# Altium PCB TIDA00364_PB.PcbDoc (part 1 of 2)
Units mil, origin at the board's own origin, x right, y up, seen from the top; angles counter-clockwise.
Board outline 10630 x 4425 mil, 2 copper layers (Top Layer, Metal), stack 128.78 mil thick; 244 components, 79 nets, 527 pads, 0 vias.
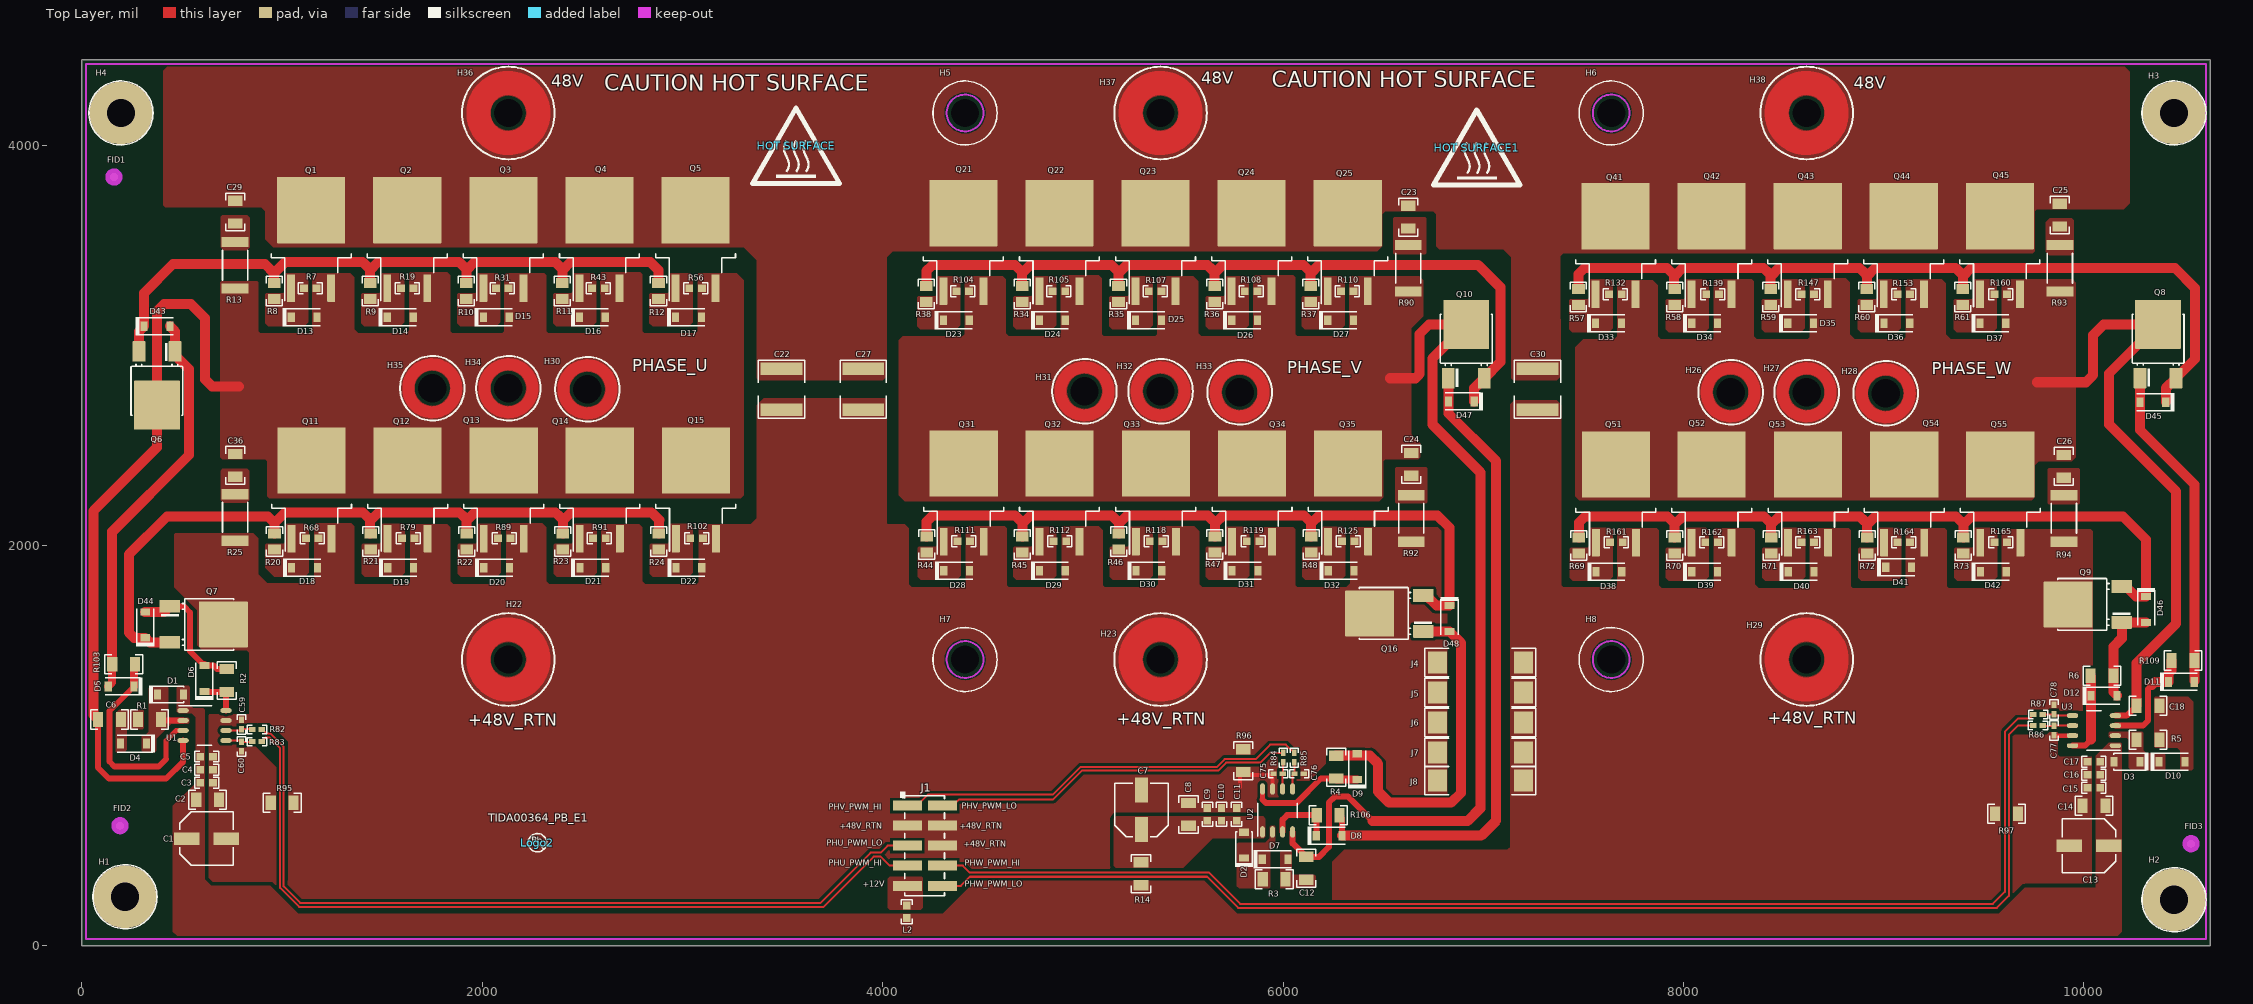
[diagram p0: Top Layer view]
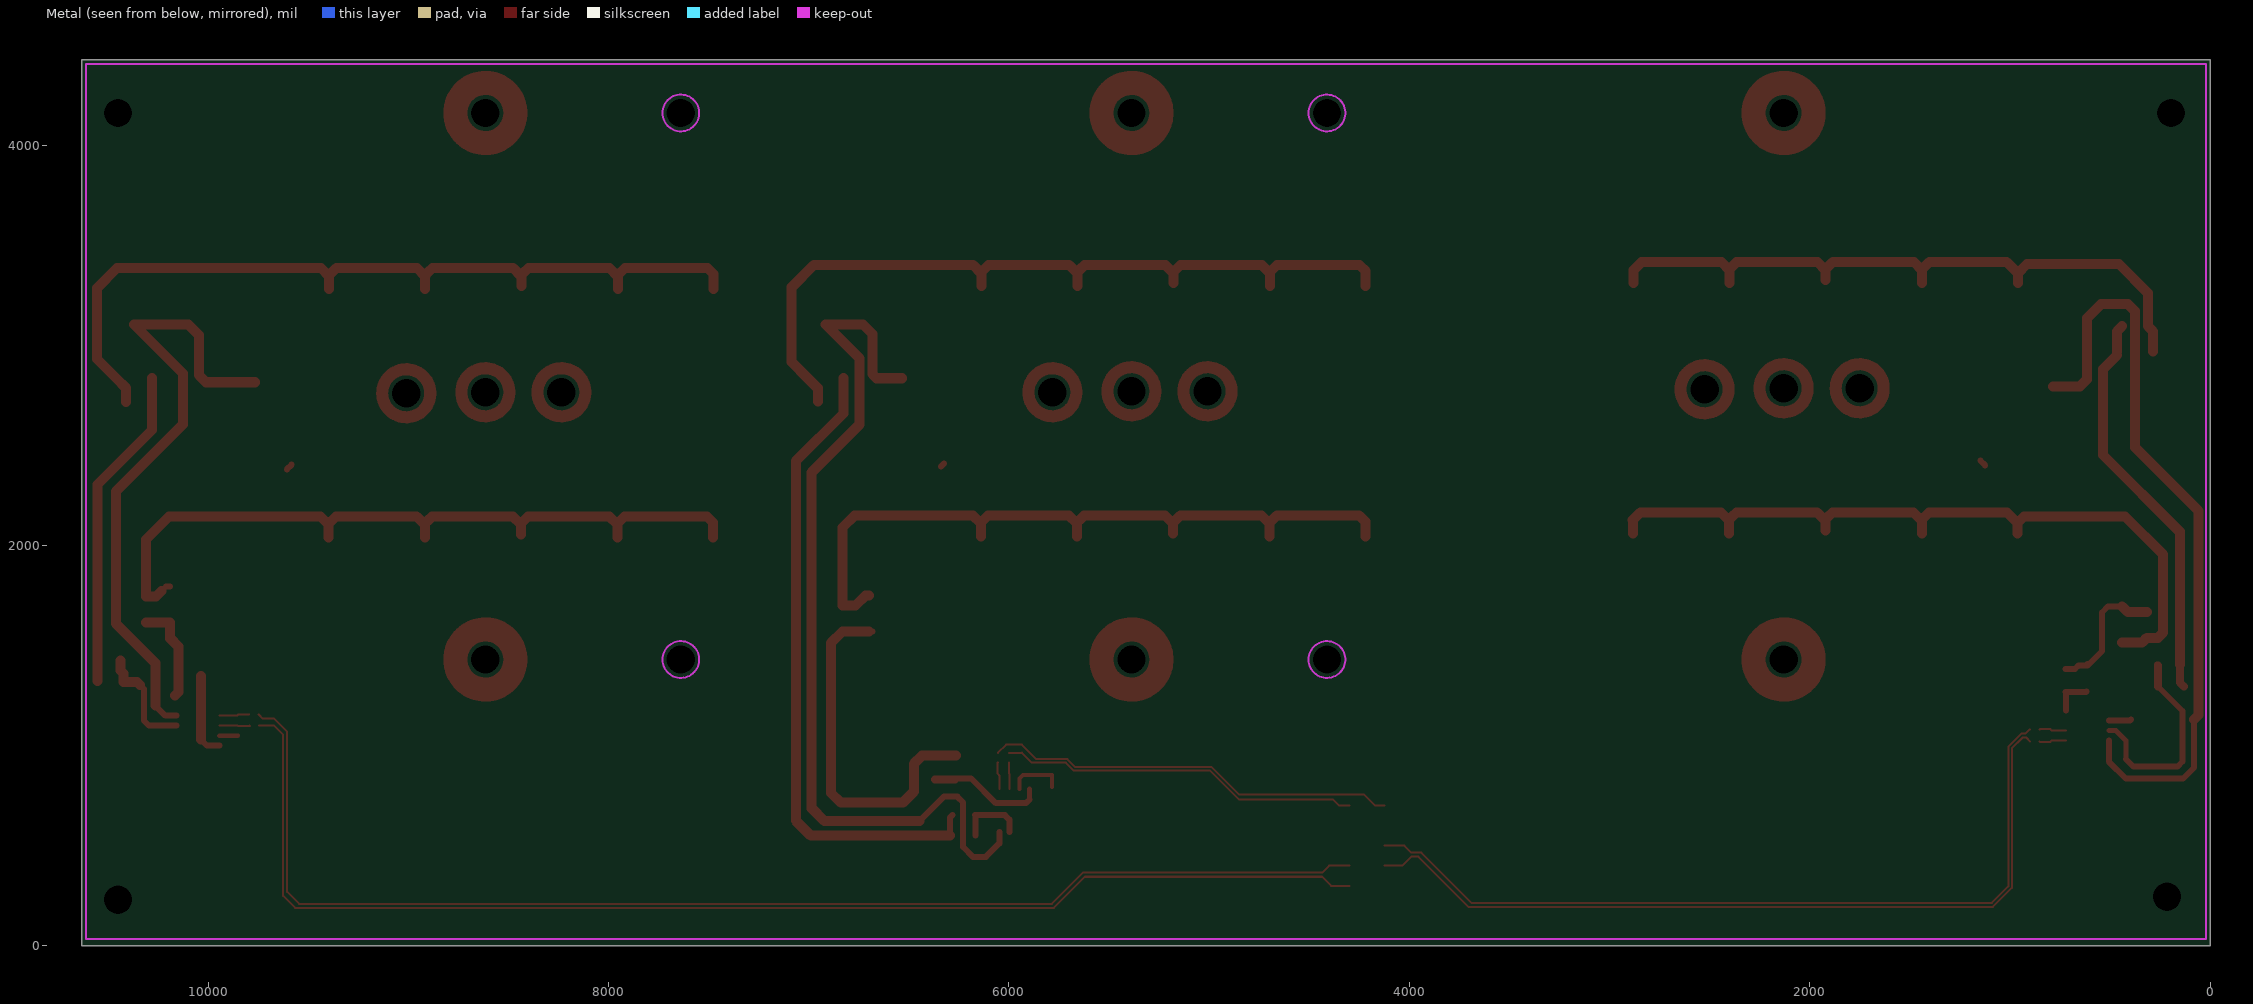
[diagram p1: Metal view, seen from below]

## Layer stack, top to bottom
Top Solder: solder mask 0.4, Solder Resist, Dk 3.5
Top Layer: signal copper 2.8
Dielectric1: core 7.87, Isolated Thermal conductive, Dk 4.8
Metal: signal copper 118.11
Bottom Solder: solder mask 0.4, Solder Resist, Dk 3.5

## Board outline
0,0 0,4425 10630,4425 10630,0

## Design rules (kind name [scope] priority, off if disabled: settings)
AcuteAngle [All] p1: minimum=4.50000000000000E+0001 checktracksonly=FALSE
AssemblyTestPointUsage [All] p1: valid=2
Clearance Clearance_PhaseW [(InNet('PHASE_W') AND InNet('PHW_PWM_HI_DRV'))] p1: gap=30
Clearance Clearance_PhaseV [(InNet('PHASE_V') AND InNet('PHV_PWM_HI_DRV'))] p2: gap=30
Clearance Clearance_phaseU [(InNet('PHASE_U') AND InNet('PHU_PWM_HI_DRV'))] p3: gap=30
Clearance Clearance_keepout [IsKeepOut vs InPolygon] p4: gap=5
Clearance Clearance_MTG_COPPER [InPadClass('MTG') vs InPolygon] p5: gap=40
Clearance "Shape to Shape" [InPolygon vs InPolygon] p6: gap=20
Clearance "shape to all" [InPolygon] p7: gap=15
Clearance Clearance_Boardedge_poly [OnCopper and InPolygon vs IsKeepOut] p8: gap=15
Clearance "Clearance_via_thr pin" [IsVia vs IsThruPin] p9: gap=8
Clearance "Clearance_pad _class" [InPadClass('u12,u4,u5')] p10: gap=7.8
Clearance "SMD to Via" [IsSMTPin vs IsVia] p11: gap=8
Clearance [All] p12: gap=8
Clearance Clearance_U5 [InPadClass('u12,u4,u5') vs IsPad] p13: gap=7.87
DiffPairsRouting DiffPair_DiffPairsRouting [InDifferentialPair ('kan')] p1: maxlimit=10 minlimit=10 mostfreqgap=10 toplayer_minwidth=15 toplayer_maxwidth=15 toplayer_prefwidth=15 bottomlayer_minwidth=15 bottomlayer_maxwidth=15 bottomlayer_prefwidth=15 maxuncoupledlength=500
DiffPairsRouting DiffPair_DiffPairsRouting_1 [InDifferentialPair ('kan')] p2: maxlimit=10 minlimit=10 mostfreqgap=10 toplayer_minwidth=15 toplayer_maxwidth=15 toplayer_prefwidth=15 bottomlayer_minwidth=15 bottomlayer_maxwidth=15 bottomlayer_prefwidth=15 maxuncoupledlength=500
DiffPairsRouting [All] p3: maxlimit=100 minlimit=10 mostfreqgap=10 toplayer_minwidth=15 toplayer_maxwidth=15 toplayer_prefwidth=15 bottomlayer_minwidth=15 bottomlayer_maxwidth=15 bottomlayer_prefwidth=15 maxuncoupledlength=1000
FabricationTestPointUsage TestPointUsage [All] p1: valid=2 allowmultiple=FALSE
FabricationTestpoint Testpoint [All] p1: side=3 testpointundercomponent=TRUE minsize=40 maxsize=100 preferedsize=60 minholesize=0 maxholesize=40 preferedholesize=32 testpointgrid=1 allowsidetop=TRUE allowsidebottom=TRUE usegrid=TRUE gridtolerance=0.01
FanoutControl Fanout_LCC [IsLCC] p1: bgadir=Out bgaviamode=Centered fanoutstyle=Auto fanoutdirection=Alternating viagrid=1 // Fanout_LCC (Default Rule)
FanoutControl Fanout_BGA [IsBGA] p2: bgadir=Out bgaviamode=Centered fanoutstyle=Auto fanoutdirection=Alternating viagrid=1 // Fanout_BGA (Default Rule)
FanoutControl Fanout_Default [All] p4: bgadir=Out bgaviamode=Centered fanoutstyle=Auto fanoutdirection=Alternating viagrid=1 // Fanout_Default (Default Rule)
FanoutControl Fanout_Small [(CompPinCount < 5)] p5: bgadir=Out bgaviamode=Centered fanoutstyle=Auto fanoutdirection=OutThenIn viagrid=1 // Fanout_Small (Default Rule)
HoleSize [All] p1: absolutevalues=TRUE maxlimit=500 minlimit=7 maxpercent=80.000 minpercent=20.000
MatchedLengths DiffPair_MatchedLengths [InDifferentialPair ('kan')] p1: tolerance=1000 checknetsindiffpair=TRUE checkdiffpairvsdiffpair=FALSE checkxsignals=FALSE checkothers=FALSE
MatchedLengths DiffPair_MatchedLengths_1 [InDifferentialPair ('kan')] p2: tolerance=1000 checknetsindiffpair=TRUE checkdiffpairvsdiffpair=FALSE checkxsignals=FALSE checkothers=FALSE
MinimumAnnularRing [All] p1: minimumring=5
MinimumAnnularRing MinimumAnnularRing_ThermalPadVias [IsVia and InAnyComponent] p2: minimumring=5.91
MinimumSolderMaskSliver MinimumSolderMaskSliver_Logo [InComponentClass('Logo') vs InComponentClass('Logo')] p1: minsoldermaskwidth=0.7
MinimumSolderMaskSliver [All] p2: minsoldermaskwidth=3.94
PlaneClearance [All] p1: clearance=15
PlaneConnect [All] p1: planeconnectstyle=Direct reliefexpansion=10 reliefentries=4 reliefconductorwidth=10 reliefairgap=10
PolygonConnect [All] p1: connectstyle=Direct reliefconductorwidth=10 reliefentries=4 polygonreliefangle="90 Angle" airgapwidth=10
RoutingVias RoutingVias_power [InNetClass('POWER')] p1: holewidth=12 width=24 viastyle="Through Hole" minholewidth=7.87 minwidth=19.68 maxholewidth=24 maxwidth=34
RoutingVias ThermalPadVias [IsVia and InAnyComponent] p2: holewidth=8 width=20 viastyle="Through Hole" minholewidth=7.87 minwidth=19 maxholewidth=24 maxwidth=34
RoutingVias [All] p3: holewidth=16 width=32 viastyle="Through Hole" minholewidth=12 minwidth=24 maxholewidth=24 maxwidth=34
SMDToCorner [All] p1: distance=30000
SilkToSilkClearance [All] p1: silktosilkclearance=5
SilkToSolderMaskClearance SilkscreenOverComponentPads [IsPad] p1: minsilkscreentomaskgap=5 clearancetoexposedcopper=TRUE
SolderMaskExpansion [All] p1: expansion=3
Width Width_power [InNetClass('POWER')] p1: maxlimit=100 minlimit=8 preferedwidth=20
Width [All] p2: maxlimit=900 minlimit=10 preferedwidth=10 checkconnectedcopper=TRUE
16 further rules are at their usual default settings.

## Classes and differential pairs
component class TIDA00364_PB_PhaseW: C25 C26 C30 D33 D34 D35 D36 D37 D38 D39 D40 D41 D42 Q41 Q42 Q43 Q44 Q45 Q51 Q52 Q53 Q54 Q55 R57 R58 R59 R60 R61 R69 R70 R71 R72 R73 R93 R94 R132 R139 R147 R153 R160 R161 R162 R163 R164 R165
component class TIDA00364_PB_PhaseV: C23 C24 C27 D23 D24 D25 D26 D27 D28 D29 D30 D31 D32 Q21 Q22 Q23 Q24 Q25 Q31 Q32 Q33 Q34 Q35 R34 R35 R36 R37 R38 R44 R45 R46 R47 R48 R90 R92 R104 R105 R107 R108 R110 R111 R112 R118 R119 R125
component class TIDA00364_PB_PhaseU: C22 C29 C36 D13 D14 D15 D16 D17 D18 D19 D20 D21 D22 Q1 Q2 Q3 Q4 Q5 Q11 Q12 Q13 Q14 Q15 R7 R8 R9 R10 R11 R12 R13 R19 R20 R21 R22 R23 R24 R25 R31 R43 R56 R68 R79 R89 R91 R102
component class TIDA00364_PB_Hardware: FID1 FID2 FID3 H1 H2 H3 H4 H5 H6 H7 H8 H22 H23 H26 H27 H28 H29 H30 H31 H32 H33 H34 H35 H36 H37 H38 "HOT SURFACE" "HOT SURFACE1" J1 J4 J5 J6 J7 J8 L2 Logo2 R14 ZZ1 ZZ2 ZZ3
component class TIDA00364_PB_GateDriver: C1 C2 C3 C4 C5 C6 C7 C8 C9 C10 C11 C12 C13 C14 C15 C16 C17 C18 C59 C60 C75 C76 C77 C78 D1 D2 D3 D4 D5 D6 D7 D8 D9 D10 D11 D12 D43 D44 D45 D46 D47 D48 Q6 Q7 Q8 Q9 Q10 Q16 R1 R2 R3 R4 R5 R6 R82 R83 R84 R85 R86 R87 R95 R96 R97 R103 R106 R109 U1 U2 U3
component class AssemblyNote: ZZ1 ZZ2 ZZ3
component class FiducialMark: FID1 FID2 FID3
component class Header: J1

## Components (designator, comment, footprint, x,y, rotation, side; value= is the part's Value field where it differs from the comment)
C1 "EEE-FK1V101XP" SM_RADIAL_D8 622.57,535.43 r0 top
C2 "GRM31CR71E475KA88L" 1206 627.57,730.43 r0 top
C3 "C1608X7R1E104K" 0603 622.57,815.43 r180 top
C4 "C1608X7R1H103K" 0603 622.57,880.43 r0 top
C5 "GRM188R71H102KA01D" 0603 622.57,945.43 r0 top
C6 "C3216X7R1H105K160AB" 1206 137.57,1130.43 r180 top
C7 "EEE-FK1V101XP" SM_RADIAL_D8 5292.6,679.24 r90 top
C8 "GRM31CR71E475KA88L" 1206 5527.12,656.24 r90 top
C9 "C1608X7R1E104K" 0603 5622.12,656.24 r270 top
C10 "C1608X7R1H103K" 0603 5692.12,656.24 r90 top
C11 "GRM188R71H102KA01D" 0603 5767.12,656.24 r90 top
C12 "C3216X7R1H105K160AB" 1206 6114.64,387.64 r90 top
C13 "EEE-FK1V101XP" SM_RADIAL_D8 10025,500 r180 top
C14 "GRM31CR71E475KA88L" 1206 10050,700 r180 top
C15 "C1608X7R1E104K" 0603 10050,790 r0 top
C16 "C1608X7R1H103K" 0603 10050,855 r180 top
C17 "GRM188R71H102KA01D" 0603 10050,920 r180 top
C18 "C3216X7R1H105K160AB" 1206 10320,1200 r180 top
C22 "GRM55DR72E105KW01L" 2220_200 3495,2780 r270 top
C23 "GRM31CR72E333KW03L" 1206 6625,3640 r270 top
C24 "GRM31CR72E333KW03L" 1206 6640,2405 r270 top
C25 "GRM31CR72E333KW03L" 1206 9880,3650 r270 top
C26 "GRM31CR72E333KW03L" 1206 9900,2395 r270 top
C27 "GRM55DR72E105KW01L" 2220_200 3902.64,2780 r270 top
C29 "GRM31CR72E333KW03L" 1206 765,3665 r270 top
C30 "GRM55DR72E105KW01L" 2220_200 7270,2780 r270 top
C36 "GRM31CR72E333KW03L" 1206 765,2400 r270 top
C59 "C0402C101J3GACTU" 0402 797.57,1105.43 r90 top
C60 "C0402C101J3GACTU" 0402 797.57,995.43 r270 top
C75 "C0402C101J3GACTU" 0402 5975,860 r180 top
C76 "C0402C101J3GACTU" 0402 6080,860 r0 top
C77 "C0402C101J3GACTU" 0402 9850.5,1075 r270 top
C78 "C0402C101J3GACTU" 0402 9850,1180 r90 top
D1 "MBR2H200SFT1G" SOD-123FL 442.57,1255.43 r0 top
D2 "MBR2H200SFT1G" SOD-123FL 5804.64,502.64 r90 top
D3 "MBR2H200SFT1G" SOD-123FL 10215,920 r180 top
D4 "B0530W-7-F" SOD-123 257.57,1010.43 r180 top
D5 "B0530W-7-F" SOD-123 195.57,1295.43 r180 top
D6 "B0530W-7-F" SOD-123 612,1335 r90 top
D7 "B0530W-7-F" SOD-123 5959.64,432.64 r0 top
D8 "B0530W-7-F" SOD-123 6230,550 r0 top
D9 "B0530W-7-F" SOD-123 6370,895 r90 top
D10 "B0530W-7-F" SOD-123 10440,920 r0 top
D11 "B0530W-7-F" SOD-123 10487,1318 r0 top
D12 "B0530W-7-F" SOD-123 10100,1250 r0 top
D13 "B0530W-7-F" SOD-123 1110,3140 r0 top
D14 "B0530W-7-F" SOD-123 1590,3140 r0 top
D15 "B0530W-7-F" SOD-123 2070,3140 r0 top
D16 "B0530W-7-F" SOD-123 2550,3140 r0 top
D17 "B0530W-7-F" SOD-123 3030,3140 r0 top
D18 "B0530W-7-F" SOD-123 1111.89,1889.21 r0 top
D19 "B0530W-7-F" SOD-123 1591.89,1889.21 r0 top
D20 "B0530W-7-F" SOD-123 2071.89,1889.21 r0 top
D21 "B0530W-7-F" SOD-123 2551.89,1889.21 r0 top
D22 "B0530W-7-F" SOD-123 3031.89,1889.21 r0 top
D23 "B0530W-7-F" SOD-123 4367.64,3125 r0 top
D24 "B0530W-7-F" SOD-123 4847.64,3125 r0 top
D25 "B0530W-7-F" SOD-123 5327.64,3125 r0 top
D26 "B0530W-7-F" SOD-123 5807.64,3125 r0 top
D27 "B0530W-7-F" SOD-123 6287.64,3125 r0 top
D28 "B0530W-7-F" SOD-123 4369.53,1874.21 r0 top
D29 "B0530W-7-F" SOD-123 4847.64,1874.21 r0 top
D30 "B0530W-7-F" SOD-123 5329.53,1874.21 r0 top
D31 "B0530W-7-F" SOD-123 5809.53,1874.21 r0 top
D32 "B0530W-7-F" SOD-123 6289.53,1874.21 r0 top
D33 "B0530W-7-F" SOD-123 7625.28,3110 r0 top
D34 "B0530W-7-F" SOD-123 8105.28,3110 r0 top
D35 "B0530W-7-F" SOD-123 8585.28,3110 r0 top
D36 "B0530W-7-F" SOD-123 9065.28,3110 r0 top
D37 "B0530W-7-F" SOD-123 9545.28,3110 r0 top
D38 "B0530W-7-F" SOD-123 7627.17,1869.21 r0 top
D39 "B0530W-7-F" SOD-123 8105.28,1869.21 r0 top
D40 "B0530W-7-F" SOD-123 8587.17,1869.21 r0 top
D41 "B0530W-7-F" SOD-123 9074.47,1890 r0 top
D42 "B0530W-7-F" SOD-123 9547.17,1869.21 r0 top
D43 "B0530W-7-F" SOD-123 375,3095 r0 top
D44 "B0530W-7-F" SOD-123 316,1603 r90 top
D45 "B0530W-7-F" SOD-123 10344.47,2715.53 r180 top
D46 "B0530W-7-F" SOD-123 10310,1680 r270 top
D47 "B0530W-7-F" SOD-123 6890,2719.06 r180 top
D48 "B0530W-7-F" SOD-123 6830.94,1635 r270 top
FID1 "Fiducial" Fiducial10-20 160,3840 r90 top
FID2 "Fiducial" Fiducial10-20 190,600 r90 top
FID3 "Fiducial" Fiducial10-20 10535,510 r90 top
H1 "RM3X8MM 2701" "APM_RM3X8MM 2701"#1 215,245 r0 top
H2 "RM3X8MM 2701" "APM_RM3X8MM 2701"#1 10450,230 r0 top
H3 "RM3X8MM 2701" "APM_RM3X8MM 2701"#1 10450,4160 r0 top
H4 "RM3X8MM 2701" "APM_RM3X8MM 2701"#1 195,4160 r0 top
H5 "RM3X8MM 2701" "APM_RM3X8MM 2701"#2 4411,4160 r0 top
H6 "RM3X8MM 2701" "APM_RM3X8MM 2701"#2 7638.36,4160 r0 top
H7 "RM3X8MM 2701" "APM_RM3X8MM 2701"#2 4411,1430 r0 top
H8 "RM3X8MM 2701" "APM_RM3X8MM 2701"#2 7638.36,1430 r0 top
H22 "24438" Keystone24438 2130,1430 r0 top
H23 "24438" Keystone24438 5387.64,1430 r0 top
H26 "24438" Keystone24438 8235,2765 r0 top
H27 "24438" Keystone24438 8615,2765 r0 top
H28 "24438" Keystone24438 9010,2760 r0 top
H29 "24438" Keystone24438 8615,1430 r0 top
H30 "24438" Keystone24438 2525,2780 r0 top
H31 "24438" Keystone24438 5007.64,2770 r0 top
H32 "24438" Keystone24438 5387.64,2770 r0 top
H33 "24438" Keystone24438 5782.64,2765 r0 top
H34 "24438" Keystone24438 2130,2785 r0 top
H35 "24438" Keystone24438 1750,2785 r0 top
H36 "24438" Keystone24438 2130,4160 r0 top
H37 "24438" Keystone24438 5387.64,4160 r0 top
H38 "24438" Keystone24438 8615,4160 r0 top
"HOT SURFACE" "CAUTION HOT SURFACE" IEC_HotSurface_medium 3567,3996 r0 top
"HOT SURFACE1" "CAUTION HOT SURFACE" IEC_HotSurface_medium 6967,3987 r0 top
J1 "0015910100" Molex_0015910100 4210,500 r270 top
J4 "S1621-46R" Harwin_S1621-46R 6985,1415 r0 top
J5 "S1621-46R" Harwin_S1621-46R 6985,1265 r0 top
J6 "S1621-46R" Harwin_S1621-46R 6985,1115 r0 top
J7 "S1621-46R" Harwin_S1621-46R 6985,965 r0 top
J8 "S1621-46R" Harwin_S1621-46R 6985,825 r0 top
L2 "BLM18HE152SN1D" 0603 4120,170 r270 top
Logo2 "Pb-Free Symbol" Pb-Free_Overlay_Small 2275,515 r0 top
Q1 "CSD19536KTT" KTT0002A_N 1145,3527 r90 top
Q2 "CSD19536KTT" KTT0002A_N 1625,3527 r90 top
Q3 "CSD19536KTT" KTT0002A_N 2105,3527 r90 top
Q4 "CSD19536KTT" KTT0002A_N 2585,3527 r90 top
Q5 "CSD19536KTT" KTT0002A_N 3065,3527 r90 top
Q6 "MJD45H11RLG" DPAK 375,2835 r270 top
Q7 "MJD45H11RLG" DPAK 572.57,1605.43 r0 top
Q8 "MJD45H11RLG" DPAK 10370,2970 r90 top
Q9 "MJD45H11RLG" DPAK 10055,1705 r180 top
Q10 "MJD45H11RLG" DPAK 6914.8,2969.06 r90 top
Q11 "CSD19536KTT" KTT0002A_N 1146.89,2276.21 r90 top
Q12 "CSD19536KTT" KTT0002A_N 1626.89,2276.21 r90 top
Q13 "CSD19536KTT" KTT0002A_N 2106.89,2276.21 r90 top
Q14 "CSD19536KTT" KTT0002A_N 2586.89,2276.21 r90 top
Q15 "CSD19536KTT" KTT0002A_N 3066.89,2276.21 r90 top
Q16 "MJD45H11RLG" DPAK 6565.94,1660 r180 top
Q21 "CSD19536KTT" KTT0002A_N 4402.64,3512 r90 top
Q22 "CSD19536KTT" KTT0002A_N 4882.64,3512 r90 top
Q23 "CSD19536KTT" KTT0002A_N 5362.64,3512 r90 top
Q24 "CSD19536KTT" KTT0002A_N 5842.64,3512 r90 top
Q25 "CSD19536KTT" KTT0002A_N 6322.64,3512 r90 top
Q31 "CSD19536KTT" KTT0002A_N 4404.53,2261.21 r90 top
Q32 "CSD19536KTT" KTT0002A_N 4882.64,2261.21 r90 top
Q33 "CSD19536KTT" KTT0002A_N 5364.53,2261.21 r90 top
Q34 "CSD19536KTT" KTT0002A_N 5844.53,2261.21 r90 top
Q35 "CSD19536KTT" KTT0002A_N 6324.53,2261.21 r90 top
Q41 "CSD19536KTT" KTT0002A_N 7660.28,3497 r90 top
Q42 "CSD19536KTT" KTT0002A_N 8140.28,3497 r90 top
Q43 "CSD19536KTT" KTT0002A_N 8620.28,3497 r90 top
Q44 "CSD19536KTT" KTT0002A_N 9100.28,3497 r90 top
Q45 "CSD19536KTT" KTT0002A_N 9580.28,3497 r90 top
Q51 "CSD19536KTT" KTT0002A_N 7662.17,2256.21 r90 top
Q52 "CSD19536KTT" KTT0002A_N 8140.28,2256.21 r90 top
Q53 "CSD19536KTT" KTT0002A_N 8622.17,2256.21 r90 top
Q54 "CSD19536KTT" KTT0002A_N 9102.17,2256.21 r90 top
Q55 "CSD19536KTT" KTT0002A_N 9582.17,2256.21 r90 top
R1 "CRCW12062R00FKEA" 1206 337.57,1130.43 r180 top
R2 "CRCW120624R0JNEA" 1206 722.57,1325.43 r90 top
R3 "CRCW12062R00FKEA" 1206 5955,332.64 r0 top
R4 "CRCW120624R0JNEA" 1206 6265,892.64 r90 top
R5 "CRCW12062R00FKEA" 1206 10320,1030 r0 top
R6 "CRCW120624R0JNEA" 1206 10090,1350 r0 top
R7 "CRCW060310K0FKEA" 0603 1140,3285 r180 top
R8 "CRCW08058R20JNEA" 0805_HV 960,3270 r90 top
R9 "CRCW08058R20JNEA" 0805_HV 1440,3270 r90 top
R10 "CRCW08058R20JNEA" 0805_HV 1920,3270 r90 top
R11 "CRCW08058R20JNEA" 0805_HV 2400,3270 r90 top
R12 "CRCW08058R20JNEA" 0805_HV 2880,3270 r90 top
R13 "CRCW25121R00FKEG" 2512 765,3400 r90 top
R14 "CRCW12060000Z0EA" 1206 5290,360 r90 top
R19 "CRCW060310K0FKEA" 0603 1625,3285 r180 top
R20 "CRCW08058R20JNEA" 0805_HV 961.89,2019.21 r90 top
R21 "CRCW08058R20JNEA" 0805_HV 1441.89,2019.21 r90 top
R22 "CRCW08058R20JNEA" 0805_HV 1921.89,2019.21 r90 top
R23 "CRCW08058R20JNEA" 0805_HV 2401.89,2019.21 r90 top
R24 "CRCW08058R20JNEA" 0805_HV 2881.89,2019.21 r90 top
R25 "CRCW25121R00FKEG" 2512 765,2140 r90 top
R31 "CRCW060310K0FKEA" 0603 2100,3285 r180 top
R34 "CRCW08058R20JNEA" 0805_HV 4697.64,3255 r90 top
R35 "CRCW08058R20JNEA" 0805_HV 5177.64,3255 r90 top
R36 "CRCW08058R20JNEA" 0805_HV 5657.64,3255 r90 top
R37 "CRCW08058R20JNEA" 0805_HV 6137.64,3255 r90 top
R38 "CRCW08058R20JNEA" 0805_HV 4217.64,3255 r90 top
R43 "CRCW060310K0FKEA" 0603 2580,3285 r180 top
R44 "CRCW08058R20JNEA" 0805_HV 4219.53,2004.21 r90 top
R45 "CRCW08058R20JNEA" 0805_HV 4697.64,2004.21 r90 top
R46 "CRCW08058R20JNEA" 0805_HV 5179.53,2019.21 r90 top
R47 "CRCW08058R20JNEA" 0805_HV 5659.53,2004.21 r90 top
R48 "CRCW08058R20JNEA" 0805_HV 6139.53,2004.21 r90 top
R56 "CRCW060310K0FKEA" 0603 3065,3285 r180 top
R57 "CRCW08058R20JNEA" 0805_HV 7475.28,3240 r90 top
R58 "CRCW08058R20JNEA" 0805_HV 7955.28,3240 r90 top
R59 "CRCW08058R20JNEA" 0805_HV 8435.28,3240 r90 top
R60 "CRCW08058R20JNEA" 0805_HV 8915.28,3240 r90 top
R61 "CRCW08058R20JNEA" 0805_HV 9395.28,3240 r90 top
R68 "CRCW060310K0FKEA" 0603 1150,2035 r180 top
R69 "CRCW08058R20JNEA" 0805_HV 7477.17,1999.21 r90 top
R70 "CRCW08058R20JNEA" 0805_HV 7955.28,1999.21 r90 top
R71 "CRCW08058R20JNEA" 0805_HV 8437.17,1999.21 r90 top
R72 "CRCW08058R20JNEA" 0805_HV 8917.17,1999.21 r90 top
R73 "CRCW08058R20JNEA" 0805_HV 9397.17,1999.21 r90 top
R79 "CRCW060310K0FKEA" 0603 1630,2035 r180 top
R82 "CRCW04022K00FKED" 0402 875,1080 r0 top
R83 "CRCW04022K00FKED" 0402 875,1020 r0 top
R84 "CRCW04022K00FKED" 0402 6000,940 r90 top
R85 "CRCW04022K00FKED" 0402 6055,940 r90 top
R86 "CRCW04022K00FKED" 0402 9770,1100 r180 top
R87 "CRCW04022K00FKED" 0402 9771.13,1155.39 r180 top
R89 "CRCW060310K0FKEA" 0603 2110,2035 r180 top
R90 "CRCW25121R00FKEG" 2512 6625,3385 r90 top
R91 "CRCW060310K0FKEA" 0603 2585,2035 r180 top
R92 "CRCW25121R00FKEG" 2512 6640,2135 r90 top
R93 "CRCW25121R00FKEG" 2512 9880,3385 r90 top
R94 "CRCW25121R00FKEG" 2512 9900,2135 r90 top
R95 "CRCW12060000Z0EA" 1206 1000,715 r0 top
R96 "CRCW12060000Z0EA" 1206 5800,925 r90 top
R97 "CRCW12060000Z0EA" 1206 9612.91,660 r180 top
R102 "CRCW060310K0FKEA" 0603 3070,2035 r180 top
R103 "CRCW120624R0JNEA" 1206 208.48,1405.43 r180 top
R104 "CRCW060310K0FKEA" 0603 4400,3270 r180 top
R105 "CRCW060310K0FKEA" 0603 4880,3270 r180 top
R106 "CRCW120624R0JNEA" 1206 6225,652.64 r0 top
R107 "CRCW060310K0FKEA" 0603 5360,3270 r180 top
R108 "CRCW060310K0FKEA" 0603 5840,3270 r180 top
R109 "CRCW120624R0JNEA" 1206 10495,1425 r0 top
R110 "CRCW060310K0FKEA" 0603 6320,3270 r180 top
R111 "CRCW060310K0FKEA" 0603 4405,2020 r180 top
R112 "CRCW060310K0FKEA" 0603 4885,2020 r180 top
R118 "CRCW060310K0FKEA" 0603 5365,2020 r180 top
R119 "CRCW060310K0FKEA" 0603 5850,2020 r180 top
R125 "CRCW060310K0FKEA" 0603 6325,2020 r180 top
R132 "CRCW060310K0FKEA" 0603 7660,3255 r180 top
R139 "CRCW060310K0FKEA" 0603 8145,3255 r180 top
R147 "CRCW060310K0FKEA" 0603 8620,3255 r180 top
R153 "CRCW060310K0FKEA" 0603 9100,3255 r180 top
R160 "CRCW060310K0FKEA" 0603 9585,3255 r180 top
R161 "CRCW060310K0FKEA" 0603 7665,2015 r180 top
R162 "CRCW060310K0FKEA" 0603 8140,2015 r180 top
R163 "CRCW060310K0FKEA" 0603 8620,2015 r180 top
R164 "CRCW060310K0FKEA" 0603 9100,2015 r180 top
R165 "CRCW060310K0FKEA" 0603 9585,2015 r180 top
U1 "UCC27211D" D0008A_N 612.57,1100.43 r0 top
U2 "UCC27211D" D0008A_N 5972.12,676.24 r90 top
U3 "UCC27211D" D0008A_N 10050,1075 r180 top
ZZ1 "These assemblies are ESD sensitive, ESD precautions shall be observed." AssemblyNote 670,4755 r0 top
ZZ2 "These assemblies must be clean and free from flux and all contaminants. Use of no clean flux is not acceptable." AssemblyNote 670,4700 r0 top
ZZ3 "These assemblies must comply with workmanship standards IPC-A-610 Class 2, unless otherwise specified." AssemblyNote 670,4650 r0 top

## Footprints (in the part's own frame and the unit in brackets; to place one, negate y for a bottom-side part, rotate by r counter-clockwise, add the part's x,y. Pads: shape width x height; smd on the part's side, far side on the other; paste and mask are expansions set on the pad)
0402 [mm] "0402 from SM-752 data"
  rect 0.8x0.6 smd: 1(-0.6,0) 2(0.6,0)
  silkscreen extent -1.22,-0.52 1.22,0.52, body extent -0.55,-0.3 0.55,0.3, height 0.6
0603 [mm] "0603 from SM-752 data"
  rect 1x0.95 smd: 1(-0.8,0) 2(0.8,0)
  silkscreen extent -1.52,-0.69 1.52,0.69, body extent -0.87,-0.47 0.87,0.47, height 1
0805_HV [mil] "0805 with 30mil clearance between pads"
  rect 50x63 smd: 1(-40,0) 2(40,0)
  silkscreen extent -74,-40 74,40, body extent -43,-29 43,29, height 57
1206 [mm] "1206 from SM-752 data"
  rect 1.3x1.85 smd: 1(-1.45,0) 2(1.45,0)
  silkscreen extent -2.4,-1.21 2.4,1.21, body extent -1.7,-0.9 1.7,0.9, height 1.35
2220_200 [mm] "Chip Capacitor, Body 5.7x5.0mm, IPC Medium Density"
  rect 1.6x5.3 smd: 1(-2.6,0) 2(2.6,0)
  silkscreen extent -3.69,-2.94 3.69,2.94, body extent -2.95,-2.62 2.95,2.62, height 1.35
2512 [mm] "Chip Resistor, Body 6.3x3.2mm, IPC Medium Density"
  rect 1.3x3.4 smd: 1(-2.95,0) 2(2.95,0)
  silkscreen extent -1.9,-1.6 1.9,1.6, body extent -3.22,-1.67 3.22,1.67, height 0.71
"APM_RM3X8MM 2701"#1 [mm] "Screw, Dia 6.7mm, Length 8mm, TH"
  round 8 / inner round 0 / far side round 0 hole 3.6 unplated: ""(0,0)
  silkscreen extent -4.06,-4.06 4.06,4.06, body extent -3.32,-3.34 3.35,3.34, height 2.38
"APM_RM3X8MM 2701"#2 [mm] "Screw, Dia 6.7mm, Length 8mm, TH"
  round 0 hole 3.6 unplated: ""(0,0)
  silkscreen extent -4.06,-4.06 4.06,4.06, body extent -3.32,-3.34 3.35,3.34, height 2.38
AssemblyNote [mil] "Assembly Note"
D0008A_N [mm] "SOIC, 8-Leads, Body 4.9x3.9mm, Pitch 1.27mm, IPC Medium Density"
  oval 1.45x0.6 smd: 1(-2.725,1.905) 2(-2.725,0.635) 3(-2.725,-0.635) 4(-2.725,-1.905) 5(2.725,-1.905) 6(2.725,-0.635) 7(2.725,0.635) 8(2.725,1.905)
  silkscreen extent -3.3,-2.5 0.9,2.5, body extent -3,-3.34 3,1.56, height 1.63
DPAK [mm] "D-PAK, 3-Pads, Body 6.22x6.73mm (max), TO-252AA using nominal STEP model"
  rrect6% 2.6x1.6 smd: 1(-3.4,2.28) 3(-3.4,-2.28)
  rrect2% 6.2x5.8 smd paste-2.9: 4(3.4,0)
  silkscreen extent -4.5,-3.3 4.7,3.28, body extent -3.86,-3.29 5.84,3.29, height 2.48
Fiducial10-20 [mm]
  round 1 smd mask+0.5: 1(0,0)
  Top Layer keep-out circle w1.178: c0,0 r0.5
Harwin_S1621-46R [mm] "JUMPER TIN SMD"
  rect 2.4x2.8 smd: 1(-5.45,0) 2(5.45,0)
  silkscreen extent -7.05,-1.8 7.05,1.8, body extent -6.27,-1.15 6.28,1.15, height 1.8
IEC_HotSurface_medium [mil]
  silkscreen extent -217,-188 217,188
Keystone24438 [mil] "Standoff, Aluminium, M3x0.5mm, L 25 mm"
  round 1 on Mech3: 0(0,0)
  body extent -98,-114 98,114, height 984
KTT0002A_N [mm] "D2-PAK, 2-Leads, Body 9x10.1mm, Pitch 2.54mm, Lead Span 15.1mm, IPC Medium Density"
  rrect10% 3.5x1 smd: 1(-6.15,2.54) 3(-6.15,-2.54)
  rrect1% 8.4x8.65 smd paste-4.2: 2(3.75,0)
  silkscreen extent -7.75,-5.07 -1.78,5.07, body extent -6.68,-5.08 7.62,5.08, height 4.72
Molex_0015910100 [mm] "MOLEX"
  rect 1.27x3.68 smd: 1(-5.08,-2.22) 2(-5.08,2.22) 3(-2.54,-2.22) 4(-2.54,2.22) 5(0,-2.22) 6(0,2.22) 7(2.54,-2.22) 8(2.54,2.22) 9(5.08,-2.22) 10(5.08,2.22)
  silkscreen extent -6.85,-3.12 6.35,2.5, body extent -6.35,-3.49 6.35,3.49, height 9.64
Pb-Free_Overlay_Small [mil]
  silkscreen extent -46,-46 46,46
SM_RADIAL_D8 [mm] "6.3 x 7.7mm:  Panasonic D8"
  rect 3.2x1.6 smd: 1(-2.5,0) 2(2.5,0)
  silkscreen extent -3.4,-3.4 3.4,3.4, body extent -3.4,-3.4 4.16,3.4, height 8.01
SOD-123 [mm] "On Semi recommended land pattern"
  rect 0.915x1.22 smd: 1(-1.637,0) 2(1.637,0)
  silkscreen extent -2.74,-1.17 2.03,1.17, body extent -1.93,-0.9 1.93,0.9, height 1.35
SOD-123FL [mm] "Copied from SOD-123"
  rect 0.915x1.22 smd: 1(-1.637,0) 2(1.637,0)
  silkscreen extent -2.74,-1.16 1.68,1.16, body extent -1.9,-1.66 1.9,0.14, height 1

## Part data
C1 C7 C13: "CAP, AL, 100 µF, 35 V, +/- 20%, 0.34 ohm, SMD"
C2 C8 C14: "CAP, CERM, 4.7 µF, 25 V, +/- 10%, X7R, 1206"
C3 C9 C15: "CAP, CERM, 0.1 µF, 25 V, +/- 10%, X7R, 0603"
C4 C10 C16: "CAP, CERM, 0.01 µF, 50 V, +/- 10%, X7R, 0603"
C5 C11 C17: "CAP, CERM, 1000 pF, 50 V, +/- 10%, X7R, 0603"
C6 C12 C18: "CAP, CERM, 1 µF, 50 V, +/- 10%, X7R, 1206"
C22 C27 C30: "CAP, CERM, 1 µF, 250 V, +/- 10%, X7R, 2220"
C23 C24 C25 C26 C29 C36: "CAP, CERM, 0.033 µF, 250 V, +/- 10%, X7R, 1206"
C59 C60 C75 C76 C77 C78: "CAP, CERM, 100 pF, 25 V, +/- 5%, C0G/NP0, 0402"
D1 D2 D3: "Diode, Schottky, 200 V, 2 A, SOD-123FL"
D4 D5 D6 D7 D8 D9 D10 D11 D12 D13 D14 D15 D16 D17 D18 D19 D20 D21 D22 D23 D24 D25 D26 D27 D28 D29 D30 D31 D32 D33 D34 D35 D36 D37 D38 D39 D40 D41 D42 D43 D44 D45 D46 D47 D48: "Diode, Schottky, 30 V, 0.5 A, SOD-123"
FID1 FID2 FID3: "Fiducial mark.  There is nothing to buy or mount."
H1 H2 H3 H4 H5 H6 H7 H8: "MACHINE SCREW PAN PHILLIPS M3"
H22 H23 H26 H27 H28 H29 H30 H31 H32 H33 H34 H35 H36 H37 H38: "Standoff, Hex,25mm Length, M3, Aluminum"
"HOT SURFACE" "HOT SURFACE1": library part IEC_HotSurface, "IEC 61010-1 Hot Surface Warning"
J1: "Header, 100mil, 5x2, SMT"
J4 J5 J6 J7 J8: "JUMPER TIN SMD, SMT"
L2: "Ferrite Bead, 1500 ohm @ 100 MHz, 0.5 A, 0603"
Logo2: library part Pb-Free
Q1 Q2 Q3 Q4 Q5 Q11 Q12 Q13 Q14 Q15 Q21 Q22 Q23 Q24 Q25 Q31 Q32 Q33 Q34 Q35 Q41 Q42 Q43 Q44 Q45 Q51 Q52 Q53 Q54 Q55: "MOSFET, N-CH, 100 V, 200 A, KTT0002A"
Q6 Q7 Q8 Q9 Q10 Q16: library part "MJD45H11RLG, ON Semiconductor", "Transistor, PNP, 80 V, 8 A, DPAK"
R1 R3 R5: "RES, 2.00, 1%, 0.25 W, 1206"
R2 R4 R6 R103 R106 R109: "RES, 24, 5%, 0.25 W, 1206"
R7 R19 R31 R43 R56 R68 R79 R89 R91 R102 R104 R105 R107 R108 R110 R111 R112 R118 R119 R125 R132 R139 R147 R153 R160 R161 R162 R163 R164 R165: "RES, 10.0 k, 1%, 0.1 W, 0603"
R8 R9 R10 R11 R12 R20 R21 R22 R23 R24 R34 R35 R36 R37 R38 R44 R45 R46 R47 R48 R57 R58 R59 R60 R61 R69 R70 R71 R72 R73: "RES, 8.2, 5%, 0.125 W, 0805"
R13 R25 R90 R92 R93 R94: "RES, 1.00, 1%, 1 W, AEC-Q200 Grade 0, 2512"
R14 R95 R96 R97: "RES, 0, 5%, 0.25 W, 1206"
R82 R83 R84 R85 R86 R87: "RES, 2.00 k, 1%, 0.063 W, 0402"
U1 U2 U3: "120-V Boot, 4-A Peak, High Frequency High-Side and Low-Side Driver, D0008A"
ZZ1 ZZ2 ZZ3: library part AssemblyNote

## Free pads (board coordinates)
  round 10 hole 141.73 unplated: 0(1750,2785) 0(2130,1430) 0(2130,2785) 0(2130,4160) 0(2525,2780) 0(5007.64,2770) 0(5387.64,2770) 0(5387.64,1430) 0(5387.64,4160) 0(5782.64,2765) 0(8235,2765) 0(8615,1430) 0(8615,2765) 0(8615,4160) 0(9010,2760)

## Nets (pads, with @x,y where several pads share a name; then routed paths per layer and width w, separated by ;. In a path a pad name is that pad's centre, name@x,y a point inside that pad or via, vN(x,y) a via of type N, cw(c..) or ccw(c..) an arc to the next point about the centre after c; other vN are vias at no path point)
48V: C22.1 C23.1 C25.1 C27.1 C29.1 C30.1 Q1.2 Q2.2 Q3.2 Q4.2 Q5.2 Q21.2 Q22.2 Q23.2 Q24.2 Q25.2 Q41.2 Q42.2 Q43.2 Q44.2 Q45.2 | length 2827.4
  Top Layer w120: 2280,4160 ccw(c2130,4160) 2280,4160 ; 5537.64,4160 ccw(c5387.64,4160) 5537.64,4160 ; 8765,4160 ccw(c8615,4160) 8765,4160
48V_RTN: C1.2 C2.2 C3.1 C4.2 C5.2 C7.2 C8.2 C9.1 C10.2 C11.2 C13.2 C14.2 C15.1 C16.2 C17.2 C22.2 C27.2 C30.2 C59.2 C60.2 C75.2 C76.2 C77.2 C78.2 D18.2 D19.2 D20.2 D21.2 D22.2 D28.2 D29.2 D30.2 D31.2 D32.2 D38.2 D39.2 D40.2 D41.2 D42.2 J1.3 J1.4 J1.6 J4.1 J4.2 J5.1 J5.2 J6.1 J6.2 J7.1 J7.2 J8.1 J8.2 Q7.4 Q9.4 Q11.3 Q12.3 Q13.3 Q14.3 Q15.3 Q16.4 Q31.3 Q32.3 Q33.3 Q34.3 Q35.3 Q51.3 Q52.3 Q53.3 Q54.3 Q55.3 R25.1 R68.1 R79.1 R89.1 R91.1 R92.1 R94.1 R95.1 R95.2 R96.1 R96.2 R97.1 R97.2 R102.1 R111.1 R112.1 R118.1 R119.1 R125.1 R161.1 R162.1 R163.1 R164.1 R165.1 U1.7 U2.7 U3.7 | length 3201
  Top Layer w20: 5785,792.64 5785,852.64 5929.24,852.64 5947.12,834.76 U2.7@5947.12,783.53 ; C77.2@9850.5,1051.38 C77.2@9851.88,1050
  Top Layer w23: C77.2@9851.88,1050 U3.7@9942.72,1050
  Top Layer w120: 2280,1430 ccw(c2130,1430) 2280,1430 ; 5537.64,1430 ccw(c5387.64,1430) 5537.64,1430 ; 8765,1430 ccw(c8615,1430) 8765,1430
NetC6_1: C6.1 D4.2 R1.2
NetC12_1: C12.1 D7.2 R3.2
NetC18_1: C18.1 D10.2 R5.2
NetC23_2: C23.2 R90.2
NetC24_2: C24.2 R92.2
NetC25_2: C25.2 R93.2
NetC26_2: C26.2 R94.2
NetC29_2: C29.2 R13.2
NetC36_2: C36.2 R25.2
NetC59_1: C59.1 R82.1 U1.6 | length 134.9
  Top Layer w10: U1.6@719.85,1075.43 791.19,1075.43 C59.1@797.57,1081.8 849.57,1081.8 R82.1@851.38,1080
NetC60_1: C60.1 R83.1 U1.5 | length 134.6
  Top Layer w10: U1.5@719.85,1025.43 791.19,1025.43 C60.1@797.57,1019.05 850.43,1019.05 R83.1@851.38,1020
NetC75_1: C75.1 R84.1 U2.6 | length 134
  Top Layer w10: U2.6@5997.12,783.53 5997.12,858.5 C75.1@5998.62,860 5998.62,915 R84.1@6000,916.38
NetC76_1: C76.1 R85.1 U2.5 | length 137.3
  Top Layer w10: U2.5@6047.12,783.53 6047.12,850.74 C76.1@6056.38,860 6056.38,915 R85.1@6055,916.38
NetC77_1: C77.1 R86.1 U3.6 | length 155.2
  Top Layer w10: R86.1@9790,1098.62 R86.1@9795,1098.62 ; R86.1@9793.62,1100 R86.1@9795,1098.62 ; U3.6@9942.72,1100 9851.88,1100 C77.1@9850.5,1098.62 R86.1@9795,1098.62
NetC78_1: C78.1 R87.1 U3.5 | length 151.3
  Top Layer w10: R87.1@9794.75,1155.39 9795.74,1156.38 C78.1@9850,1156.38 ; C78.1@9849.12,1155 9854.12,1150 U3.5@9942.72,1150
NetD1_1: D1.1 D4.1 R1.1 U1.2 | length 112.7
  Top Layer w30: R1.1@394.65,1130.43 399.65,1125.43 U1.2@505.28,1125.43
NetD2_1: D2.1 D7.1 R3.1 U2.2
NetD3_1: D3.1 D10.1 R5.1 U3.2
NetD5_1: D5.1 R103.1 U1.3 | length 1044.6
  Top Layer w25: 420,932.86 420,1025 470.43,1075.43 U1.3@505.28,1075.43
  Top Layer w30: D5.1@260.04,1295.43 137.57,1172.96 137.57,920.43 162.57,895.43 382.57,895.43 420,932.86 ; R103.1@260.04,1399.89 R103.1@265.57,1405.43
  Top Layer w40: D5.1@260.04,1295.43 R103.1@260.04,1399.89
NetD5_2: D5.2 D43.2 Q6.1 R103.2 | length 2006.4
  Top Layer w30: Q6.1@464.76,2950.24 Q6.1@464.76,2968.86
  Top Layer w40: D5.2@131.1,1295.43 151.39,1315.72 R103.2@151.39,1405.43
  Top Layer w50: R103.2@151.39,1405.43 151.39,2068.39 535,2452 535,2880 Q6.1@464.76,2950.24 ; D43.2@439.47,3095 464.76,3069.7 Q6.1@464.76,2968.86
NetD6_1: D6.1 R2.1 U1.8 | length 200.1
  Top Layer w30: D6.1@617.57,1270.96 620.18,1268.34 R2.1@722.57,1268.34 719.85,1265.62 U1.8@719.85,1175.43
NetD6_2: D6.2 D44.2 Q7.1 R2.2 | length 663.9
  Top Layer w30: Q7.1@438.71,1695.19 509.81,1695.19 540,1665 540,1471.47 D6.2@612,1399.47 657.53,1399.47 674.49,1382.51 R2.2@722.57,1382.51 ; D6.2@609,1408.46 D6.2@612,1408.46
  Top Layer w50: D44.2@316,1667.47 410.99,1667.47 Q7.1@438.71,1695.19
NetD8_1: D8.1 R106.1 U2.3 | length 344.7
  Top Layer w30: U2.3@5997.12,568.96 5997.12,629.76 6020,652.64 R106.1@6167.91,652.64 6165.53,650.26 D8.1@6165.53,550
NetD8_2: D8.2 D47.2 Q10.1 R106.2 | length 3217.5
  Top Layer w30: R106.2@6282.09,652.64 6294.47,640.26 D8.2@6294.47,550 ; D47.2@6825.04,2719.55 D47.2@6825.53,2719.06
  Top Layer w50: D8.2@6294.47,550 6989,550 7064,625 7064,2421 6825.53,2659.47 D47.2@6825.53,2719.06 ; D47.2@6825.04,2719.55 Q10.1@6825.04,2835.2
NetD9_1: D9.1 R4.1 U2.8 | length 586.3
  Top Layer w23: 5897.12,730.52 U2.8@5897.12,783.53
  Top Layer w30: 5897.12,730.52 5915,712.64 6065,712.64 6187.91,835.55 R4.1@6265,835.55 R4.1@6270.02,830.53
  Top Layer w40: R4.1@6270.02,830.53 D9.1@6370,830.53
NetD9_2: D9.2 D48.2 Q16.1 R4.2 | length 1802
  Top Layer w30: Q16.1@6681.18,1570.24 Q16.1@6699.8,1570.24
  Top Layer w50: R4.2@6265,949.72 6434.28,949.72 6475,909 6475,770 6530,715 6839,715 6888,764 6888,1513.48 D48.2@6830.94,1570.53 6830.65,1570.24 Q16.1@6699.8,1570.24
NetD11_1: D11.1 R109.1 U3.3 | length 561.5
  Top Layer w30: U3.3@10157.28,1100 10295,1100 10320,1125 10320,1283 10340,1303
  Top Layer w50: 10340,1303 10355,1318 D11.1@10422.53,1318 10422.53,1359.36 10437.91,1374.74 R109.1@10437.91,1425
NetD11_2: D11.2 D45.2 Q8.1 R109.2 | length 1626
  Top Layer w50: Q8.1@10280.24,2836.14 10280.24,2576.76 10552.09,2304.91 R109.2@10552.09,1425 10552.09,1323.62 D11.2@10551.47,1323
NetD12_1: D12.1 R6.1 U3.8 | length 426
  Top Layer w30: U3.8@9942.72,1000 10005,1000 10035.53,1030.53 ; R6.1@10032.91,1350 R6.1@10035.53,1347.38
  Top Layer w50: 10035.53,1030.53 D12.1@10035.53,1250 R6.1@10035.53,1347.38
NetD12_2: D12.2 D46.2 Q9.1 R6.2 | length 511
  Top Layer w50: D12.2@10164.47,1250 10147.09,1267.38 R6.2@10147.09,1350 10147.09,1494.09 10188.86,1535.86 Q9.1@10188.86,1615.24 10309.7,1615.24 D46.2@10310,1615.53
NetD13_1: D13.1 Q1.1 R7.2 R8.1
NetD14_1: D14.1 Q2.1 R9.1 R19.2
NetD15_1: D15.1 Q3.1 R10.1 R31.2
NetD16_1: D16.1 Q4.1 R11.1 R43.2
NetD17_1: D17.1 Q5.1 R12.1 R56.2
NetD18_1: D18.1 Q11.1 R20.1 R68.2
NetD19_1: D19.1 Q12.1 R21.1 R79.2
NetD20_1: D20.1 Q13.1 R22.1 R89.2
NetD21_1: D21.1 Q14.1 R23.1 R91.2
NetD22_1: D22.1 Q15.1 R24.1 R102.2
NetD23_1: D23.1 Q21.1 R38.1 R104.2
NetD24_1: D24.1 Q22.1 R34.1 R105.2
NetD25_1: D25.1 Q23.1 R35.1 R107.2
NetD26_1: D26.1 Q24.1 R36.1 R108.2
NetD27_1: D27.1 Q25.1 R37.1 R110.2
NetD28_1: D28.1 Q31.1 R44.1 R111.2
NetD29_1: D29.1 Q32.1 R45.1 R112.2
NetD30_1: D30.1 Q33.1 R46.1 R118.2
NetD31_1: D31.1 Q34.1 R47.1 R119.2
NetD32_1: D32.1 Q35.1 R48.1 R125.2
NetD33_1: D33.1 Q41.1 R57.1 R132.2
NetD34_1: D34.1 Q42.1 R58.1 R139.2
NetD35_1: D35.1 Q43.1 R59.1 R147.2
NetD36_1: D36.1 Q44.1 R60.1 R153.2
NetD37_1: D37.1 Q45.1 R61.1 R160.2
NetD38_1: D38.1 Q51.1 R69.1 R161.2
NetD39_1: D39.1 Q52.1 R70.1 R162.2
NetD40_1: D40.1 Q53.1 R71.1 R163.2
NetD41_1: D41.1 Q54.1 R72.1 R164.2
NetD42_1: D42.1 Q55.1 R73.1 R165.2
NetJ1_9: J1.9 L2.1
PHASE_U: C6.2 C36.1 D13.2 D14.2 D15.2 D16.2 D17.2 Q1.3 Q2.3 Q3.3 Q4.3 Q5.3 Q6.4 Q11.2 Q12.2 Q13.2 Q14.2 Q15.2 R7.1 R13.1 R19.1 R31.1 R43.1 R56.1 U1.4 | length 6077.6
  Top Layer w30: C6.2@80.48,1130.43 80.48,889.52 135,835 420,835 505.28,920.28 U1.4@505.28,1025.43 ; Q11.2@1123.04,2400 Q11.2@1146.89,2423.85
  Top Layer w50: C6.2@80.48,1130.43 58,1152.91 58,2173 375,2490 Q6.4@375,2701.14 375,3170 410,3205 545,3205 615,3135 615,2830 650,2795 785,2795
  Top Layer w60: 1870,2785 ccw(c1750,2785) 1870,2785 ; 2250,2785 ccw(c2130,2785) 2250,2785 ; 2645,2780 ccw(c2525,2780) 2645,2780
PHASE_V: C12.2 C24.1 D23.2 D24.2 D25.2 D26.2 D27.2 Q10.4 Q21.3 Q22.3 Q23.3 Q24.3 Q25.3 Q31.2 Q32.2 Q33.2 Q34.2 Q35.2 R90.1 R104.1 R105.1 R107.1 R108.1 R110.1 U2.4 | length 6829.3
  Top Layer w30: U2.4@6047.12,568.96 6047.12,512.24 C12.2@6114.64,444.72 6179.72,444.72 6228.88,493.88 6228.88,716.52 6257.36,745 6325,745 6446,624 ; Q35.2@6324.53,2408.85 Q35.2@6338.38,2395
  Top Layer w50: 6446,624 6922,624 6985,687 6985,2365 6745,2605 6745,2933.11 Q10.4@6914.8,3102.91 6727.91,3102.91 6681,3056 6681,2855 6661,2835 6535,2835
  Top Layer w60: 5127.64,2770 ccw(c5007.64,2770) 5127.64,2770 ; 5507.64,2770 ccw(c5387.64,2770) 5507.64,2770 ; 5902.64,2765 ccw(c5782.64,2765) 5902.64,2765
PHASE_W: C18.2 C26.1 D33.2 D34.2 D35.2 D36.2 D37.2 Q8.4 Q41.3 Q42.3 Q43.3 Q44.3 Q45.3 Q51.2 Q52.2 Q53.2 Q54.2 Q55.2 R93.1 R132.1 R139.1 R147.1 R153.1 R160.1 U3.4 | length 5490.4
  Top Layer w30: Q55.2@9582.17,2403.85 Q55.2@9606.02,2380 ; U3.4@10157.28,1150 10212.91,1150 C18.2@10262.91,1200
  Top Layer w50: 9765,2815 10010,2815 10045,2850 10045,3050 10098.86,3103.86 Q8.4@10370,3103.86 10125,2858.86 10125,2605 10461,2269 10461,1610 10262.91,1411.91 C18.2@10262.91,1200
  Top Layer w60: 8355,2765 ccw(c8235,2765) 8355,2765 ; 8735,2765 ccw(c8615,2765) 8735,2765 ; 9130,2760 ccw(c9010,2760) 9130,2760
PHU_PWM_HI: J1.7 R83.2 | length 4112.9
  Top Layer w10: R83.2@898.62,1020 919.12,1040.5 936.04,1040.5 990,986.54 990,290 1085,195 3705,195 3955,445 3990,445 4035,400 J1.7@4122.6,400
PHU_PWM_HI_DRV: D43.1 Q6.3 R8.2 R9.2 R10.2 R11.2 R12.2 | length 3390.6
  Top Layer w50: Q6.3@285.24,2968.86 285.24,3069.7 D43.1@310.53,3095 310.53,3260 455.53,3405 915,3405 960,3360 ; R8.2@960,3310 960,3360 ; R9.2@1438.11,3310 1438.11,3375 1440.61,3377.5 ; R10.2@1920,3325 1920,3375 1922.5,3377.5 ; R11.2@2400,3310 2400,3375 2402.5,3377.5 ; R12.2@2880,3310 2880,3375 2839.21,3415.79 2440.79,3415.79 2402.5,3377.5 ; 960,3360 1015.79,3415.79 1402.32,3415.79 1422.32,3395.79 1440.61,3377.5 ; 1440.61,3377.5 1478.9,3415.79 1884.21,3415.79 1904.84,3395.16 1922.5,3377.5 ; 1922.5,3377.5 1960.79,3415.79 2364.21,3415.79 2380.47,3399.53 2402.5,3377.5
PHU_PWM_LO: J1.5 R82.2 | length 4108.4
  Top Layer w10: R82.2@898.62,1080 902.5,1080 923,1059.5 942.5,1059.5 1008,994 1008,297.46 1090.46,215 3690,215 3940,465 3990,465 4025,500 J1.5@4122.6,500
PHU_PWM_LO_DRV: D44.1 Q7.3 R20.2 R21.2 R22.2 R23.2 R24.2 | length 3802.2
  Top Layer w50: Q7.3@438.71,1515.66 338.87,1515.66 D44.1@316,1538.53 260.47,1538.53 234,1565 234,1954 425,2145 928.78,2145 961.89,2111.89 ; R20.2@961.89,2059.21 961.89,2111.89 ; R21.2@1440,2059.21 1440,2124.21 1442.5,2126.71 ; R22.2@1921.89,2074.21 1921.89,2124.21 1924.39,2126.71 ; R23.2@2401.89,2059.21 2401.89,2124.21 2404.39,2126.71 ; R24.2@2881.89,2059.21 2881.89,2124.21 2884.39,2126.71 2871.1,2140 2846.1,2165 2442.68,2165 2404.39,2126.71 ; 961.89,2111.89 1015,2165 1404.21,2165 1424.21,2145 1442.5,2126.71 ; 1442.5,2126.71 1480.79,2165 1886.1,2165 1906.73,2144.37 1924.39,2126.71 ; 1924.39,2126.71 1962.68,2165 2366.1,2165 2382.36,2148.74 2404.39,2126.71
PHV_PWM_HI: J1.1 R85.2 | length 2075.9
  Top Layer w10: J1.1@4122.6,700 4170,700 4225,755 4849.54,755 4987.54,893 5667.54,893 5707.54,933 5863,933 5935,1005 6013.62,1005 R85.2@6055,963.62
PHV_PWM_HI_DRV: D47.1 Q10.3 R34.2 R35.2 R36.2 R37.2 R38.2 | length 4012.2
  Top Layer w50: R38.2@4217.64,3295 4217.64,3370.31 4248.11,3400.79 4659.96,3400.79 4679.96,3380.79 4698.25,3362.5 ; R34.2@4695.75,3295 4695.75,3360 4698.25,3362.5 ; R35.2@5177.64,3310 5177.64,3360 5180.14,3362.5 ; R36.2@5657.64,3295 5657.64,3360 5660.14,3362.5 ; R37.2@6137.64,3295 6137.64,3360 6140.14,3362.5 ; D47.1@6954.47,2719.06 6954.47,2785.1 Q10.3@7004.57,2835.2 7085,2915.63 7085,3290 6974.21,3400.79 6178.43,3400.79 6140.14,3362.5 ; 4698.25,3362.5 4736.54,3400.79 5141.85,3400.79 5162.48,3380.16 5180.14,3362.5 ; 5180.14,3362.5 5218.43,3400.79 5621.85,3400.79 5638.11,3384.53 5660.14,3362.5 ; 5660.14,3362.5 5698.43,3400.79 6101.85,3400.79 6126.85,3375.79 6140.14,3362.5
PHV_PWM_LO: J1.2 R84.2 | length 1812.9
  Top Layer w10: J1.2@4297.4,700 4350,700 4380,730 4850,730 4995,875 5675,875 5715,915 5885,915 5935,965 5936.38,963.62 R84.2@6000,963.62
PHV_PWM_LO_DRV: D48.1 Q16.3 R44.2 R45.2 R46.2 R47.2 R48.2 | length 3637.2
  Top Layer w50: R44.2@4219.53,2044.21 4219.53,2119.53 4250,2150 4661.85,2150 4681.85,2130 4700.14,2111.71 ; R45.2@4697.64,2044.21 4697.64,2109.21 4700.14,2111.71 ; R46.2@5179.53,2059.21 5179.53,2109.21 5182.03,2111.71 ; R47.2@5659.53,2044.21 5659.53,2109.21 5662.03,2111.71 ; R48.2@6139.53,2044.21 6139.53,2109.21 6142.03,2111.71 ; Q16.3@6699.8,1749.76 6715.24,1749.76 6765.53,1699.47 D48.1@6830.94,1699.47 6830.94,2074.06 ; 6830.94,2089.06 6770,2150 6180.31,2150 6142.03,2111.71 ; 4700.14,2111.71 4738.42,2150 5143.74,2150 5164.37,2129.37 5182.03,2111.71 ; 5182.03,2111.71 5220.31,2150 5623.74,2150 5640,2133.74 5662.03,2111.71 ; 5662.03,2111.71 5700.31,2150 6103.74,2150 6128.74,2125 6142.03,2111.71
PHW_PWM_HI: J1.8 R87.2 | length 6389
  Top Layer w10: J1.8@4297.4,400 4400,400 4435,365 5630,365 5785,210 9545,210 9605,270 9605,1070 9670,1135 9727.12,1135 R87.2@9747.51,1155.39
